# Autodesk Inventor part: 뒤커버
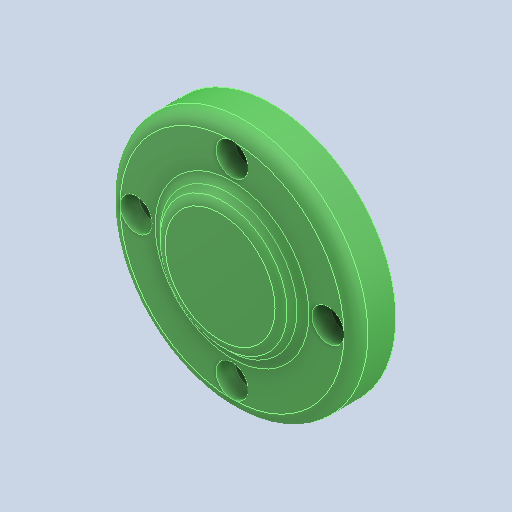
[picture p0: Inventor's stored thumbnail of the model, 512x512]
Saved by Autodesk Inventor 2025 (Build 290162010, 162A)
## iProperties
Created: 2024-07
Part Number: 뒤커버
Material: 알루미늄 6061
Document SubType Name: Modeling
Designer: 학생
Density: 2.71 g/cm^3
Appearance: 기본값
Author: jhkim
Sending System: Autodesk Inventor 2025
Preprocessor: ST-DEVELOPER v20
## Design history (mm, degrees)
feature "솔리드1"
node "솔리드2"
